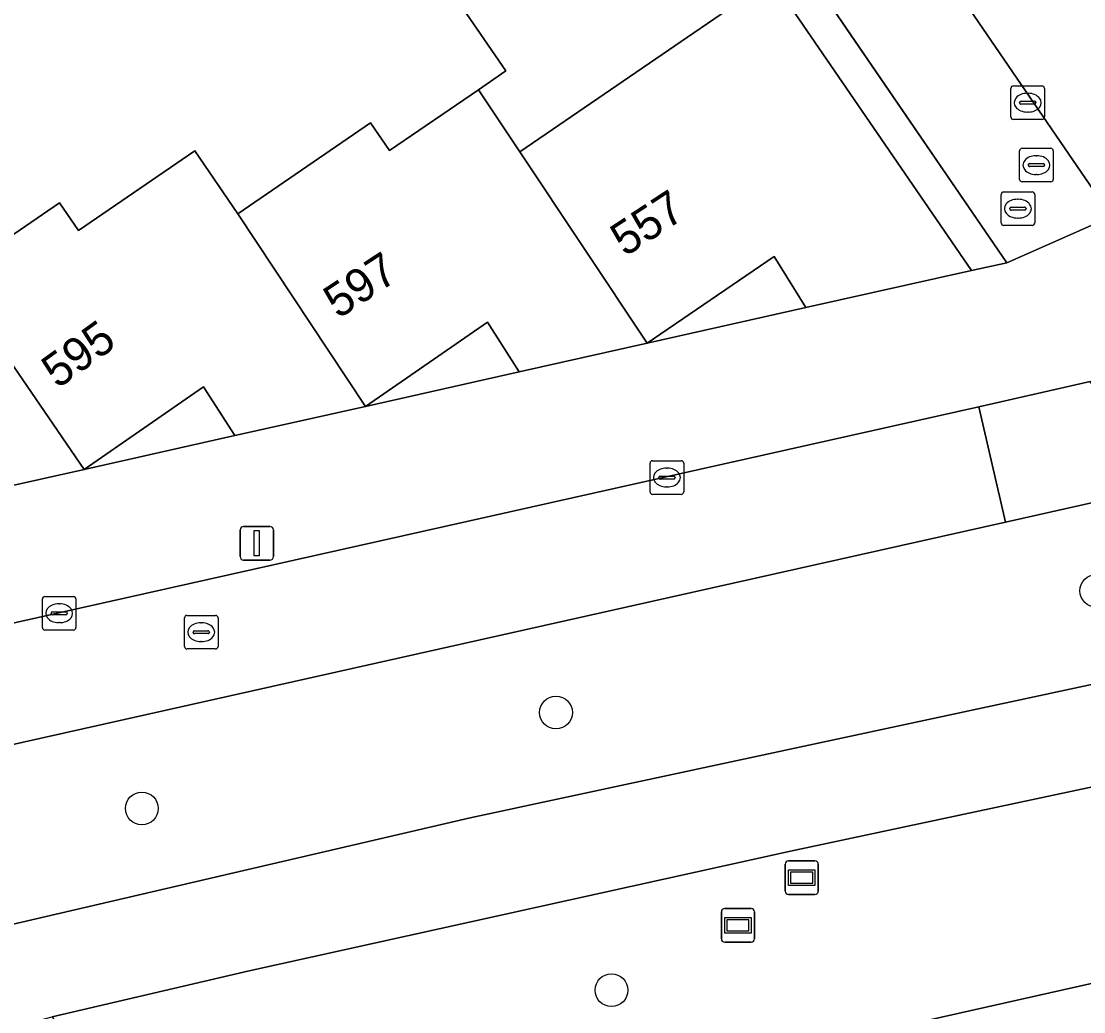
# Model space of a CAD drawing. Extents: x 155275 to 156265, y 382654 to 383635.
# Drawn here: x 155810.99 to 155842.67, y 383184.9 to 383214.43 of the extents above; entities that cross this region are included whole.
import ezdxf

# ---------------------------------------------------------------- set-up
doc = ezdxf.new("R2010")
doc.units = 0
for name, color, linetype in [('IMGEO_Berm_groen', 7, 'Continuous'), ('IMGEO_Boom', 7, 'Continuous'), ('IMGEO_Erf', 7, 'Continuous'), ('IMGEO_Fietspad_gesloten', 7, 'Continuous'), ('IMGEO_Kolk', 7, 'Continuous'), ('IMGEO_Lichtmast', 7, 'Continuous'), ('IMGEO_Pand', 7, 'Continuous'), ('IMGEO_Pand_nummerreeks', 7, 'Continuous'), ('IMGEO_Pand_overbouw', 7, 'Continuous'), ('IMGEO_Rijbaan_lokaal_gesloten', 7, 'Continuous'), ('IMGEO_Rijbaan_lokaal_open', 7, 'Continuous'), ('IMGEO_Rioolput', 7, 'Continuous'), ('IMGEO_Verklikker', 7, 'Continuous'), ('IMGEO_Voetpad_open', 7, 'Continuous')]:
    doc.layers.add(name, color=color, linetype=linetype)

msp = doc.modelspace()

# ---------------------------------------------------------------- linework, layer by layer
at = {"layer": 'IMGEO_Berm_groen'}
for points in [[(155848.276, 383195.813), (155845.025, 383200.548), (155840.331, 383199.496), (155810.33, 383192.781), (155806.938, 383192.022), (155810.141, 383187.373), (155824.371, 383190.683)], [(155849.792, 383187.297), (155853.53, 383188.156), (155850.109, 383193.138), (155833.92, 383189.687), (155817.791, 383186.119), (155811.916, 383184.748), (155815.412, 383179.591), (155819.804, 383180.555)]]:
    msp.add_lwpolyline(points, close=True, dxfattribs=at)
at = {"layer": 'IMGEO_Boom'}
for centre in [(155843.039, 383197.451), (155826.932, 383193.822), (155814.588, 383190.961), (155828.586, 383185.543)]:
    msp.add_circle(centre, 0.489, dxfattribs=at)
at = {"layer": 'IMGEO_Erf'}
for points in [[(155839.315, 383206.997), (155840.374, 383207.229), (155806.889, 383256.17), (155806.057, 383255.604), (155809.653, 383250.348), (155812.618, 383246.016), (155815.583, 383241.682), (155818.547, 383237.35), (155821.512, 383233.017), (155824.477, 383228.684), (155827.441, 383224.351), (155830.406, 383220.018), (155833.37, 383215.686)], [(155829.654, 383204.83), (155834.384, 383205.895), (155833.434, 383207.413)], [(155821.253, 383202.95), (155825.834, 383203.977), (155824.896, 383205.462)], [(155812.872, 383201.064), (155817.361, 383202.086), (155816.423, 383203.531)]]:
    msp.add_lwpolyline(points, close=True, dxfattribs=at)
msp.add_lwpolyline([(155800.38, 383217.68), (155803.347, 383213.349), (155807.304, 383207.574), (155808.057, 383208.09), (155808.925, 383206.823), (155812.132, 383209.02), (155812.697, 383208.195), (155816.162, 383210.569), (155817.448, 383208.691), (155821.408, 383211.404), (155821.973, 383210.579), (155824.618, 383212.391), (155825.438, 383212.953), (155823.731, 383215.445)], dxfattribs=at)
at = {"layer": 'IMGEO_Fietspad_gesloten'}
for points in [[(155890.991, 383205.663), (155886.832, 383204.488), (155883.25, 383203.59), (155879.663, 383202.712), (155851.768, 383196.574), (155848.276, 383195.813), (155824.371, 383190.683), (155810.141, 383187.373), (155807.023, 383186.593), (155784.144, 383180.465), (155758.942, 383174.226)], [(155803.789, 383182.688), (155808.796, 383183.946), (155811.916, 383184.748), (155817.791, 383186.119), (155833.92, 383189.687), (155850.109, 383193.138), (155853.636, 383193.872), (155881.496, 383200.022), (155885.113, 383200.876)]]:
    msp.add_lwpolyline(points, dxfattribs=at)
at = {"layer": 'IMGEO_Kolk'}
for p, q in [((155840.493, 383211.578), (155840.493, 383212.43)), ((155840.568, 383212.504), (155841.42, 383212.504)), ((155841.494, 383212.43), (155841.494, 383211.578)), ((155840.981, 383212.284), (155841.006, 383212.284)), ((155840.752, 383211.998), (155840.752, 383212.01)), ((155841.19, 383211.961), (155840.792, 383211.961)), ((155840.795, 383212.047), (155841.193, 383212.047)), ((155841.236, 383212.01), (155841.236, 383211.998)), ((155841.42, 383211.504), (155840.568, 383211.504)), ((155841.004, 383211.724), (155840.979, 383211.724)), ((155829.813, 383201.327), (155830.665, 383201.327)), ((155829.738, 383200.401), (155829.738, 383201.253)), ((155830.226, 383201.107), (155830.251, 383201.107)), ((155830.739, 383201.253), (155830.739, 383200.401)), ((155829.997, 383200.821), (155829.997, 383200.833)), ((155830.435, 383200.784), (155830.037, 383200.784)), ((155830.04, 383200.87), (155830.438, 383200.87)), ((155830.481, 383200.833), (155830.481, 383200.821)), ((155830.249, 383200.547), (155830.224, 383200.547)), ((155830.665, 383200.327), (155829.813, 383200.327)), ((155811.622, 383196.355), (155811.622, 383197.207)), ((155811.697, 383197.281), (155812.549, 383197.281)), ((155812.623, 383197.207), (155812.623, 383196.355)), ((155812.11, 383197.061), (155812.135, 383197.061)), ((155811.881, 383196.775), (155811.881, 383196.787)), ((155812.319, 383196.738), (155811.921, 383196.738)), ((155811.924, 383196.824), (155812.322, 383196.824)), ((155812.365, 383196.787), (155812.365, 383196.775)), ((155812.549, 383196.281), (155811.697, 383196.281)), ((155812.133, 383196.501), (155812.108, 383196.501))]:
    msp.add_line(p, q, dxfattribs=at)
for points in [[(155840.493, 383211.578), (155840.493, 383212.43)], [(155840.568, 383212.504), (155841.42, 383212.504)], [(155841.494, 383212.43), (155841.494, 383211.578)], [(155841.42, 383211.504), (155840.568, 383211.504)], [(155829.813, 383201.327), (155830.665, 383201.327)], [(155829.738, 383200.401), (155829.738, 383201.253)], [(155830.739, 383201.253), (155830.739, 383200.401)], [(155830.665, 383200.327), (155829.813, 383200.327)], [(155811.622, 383196.355), (155811.622, 383197.207)], [(155811.697, 383197.281), (155812.549, 383197.281)], [(155812.623, 383197.207), (155812.623, 383196.355)], [(155812.549, 383196.281), (155811.697, 383196.281)]]:
    msp.add_lwpolyline(points, dxfattribs=at)
for centre, radius, start, end in [((155840.57, 383212.428), 0.0765, 91.552, 178.448), ((155840.57, 383212.428), 0.0765, 91.552, 178.448), ((155841.418, 383212.428), 0.0765, 1.552, 88.448), ((155841.418, 383212.428), 0.0765, 1.552, 88.448), ((155840.792, 383212.007), 0.0403, 85.8775, 175.7526), ((155840.789, 383211.997), 0.0366, 178.938, 274.7102), ((155841.193, 383212.004), 0.043, 264.8664, 352.4533), ((155841.197, 383212.009), 0.0386, 1.7309, 96.639), ((155840.57, 383211.58), 0.0765, 181.552, 268.448), ((155840.57, 383211.58), 0.0765, 181.552, 268.448), ((155841.418, 383211.58), 0.0765, 271.552, 358.448), ((155841.418, 383211.58), 0.0765, 271.552, 358.448), ((155829.815, 383201.251), 0.0765, 91.552, 178.448), ((155829.815, 383201.251), 0.0765, 91.552, 178.448), ((155830.663, 383201.251), 0.0765, 1.552, 88.448), ((155830.663, 383201.251), 0.0765, 1.552, 88.448), ((155830.037, 383200.83), 0.0403, 85.8775, 175.7526), ((155830.034, 383200.82), 0.0366, 178.938, 274.7102), ((155830.438, 383200.827), 0.043, 264.8664, 352.4533), ((155830.442, 383200.832), 0.0386, 1.7309, 96.639), ((155829.815, 383200.403), 0.0765, 181.552, 268.448), ((155829.815, 383200.403), 0.0765, 181.552, 268.448), ((155830.663, 383200.403), 0.0765, 271.552, 358.448), ((155830.663, 383200.403), 0.0765, 271.552, 358.448), ((155811.699, 383197.205), 0.0765, 91.552, 178.448), ((155811.699, 383197.205), 0.0765, 91.552, 178.448), ((155812.547, 383197.205), 0.0765, 1.552, 88.448), ((155812.547, 383197.205), 0.0765, 1.552, 88.448), ((155811.921, 383196.784), 0.0403, 85.8775, 175.7526), ((155811.918, 383196.774), 0.0366, 178.938, 274.7102), ((155812.322, 383196.781), 0.043, 264.8664, 352.4533), ((155812.326, 383196.786), 0.0386, 1.7309, 96.639), ((155811.699, 383196.357), 0.0765, 181.552, 268.448), ((155811.699, 383196.357), 0.0765, 181.552, 268.448), ((155812.547, 383196.357), 0.0765, 271.552, 358.448), ((155812.547, 383196.357), 0.0765, 271.552, 358.448)]:
    msp.add_arc(centre, radius, start, end, dxfattribs=at)
for centre, major_axis, ratio, start_param, end_param in [((155840.98, 383212.004), (-0.387, 0.002), 0.722429, 4.712389, 7.853982), ((155841.005, 383212.004), (-0.39, 0.002), 0.717154, 1.570796, 4.712389), ((155830.225, 383200.827), (-0.387, 0.002), 0.722429, 4.712389, 7.853982), ((155830.25, 383200.827), (-0.39, 0.002), 0.717154, 1.570796, 4.712389), ((155812.109, 383196.781), (-0.387, 0.002), 0.722429, 4.712389, 7.853982), ((155812.134, 383196.781), (-0.39, 0.002), 0.717154, 1.570796, 4.712389)]:
    msp.add_ellipse(centre, major_axis=major_axis, ratio=ratio, start_param=start_param, end_param=end_param, dxfattribs=at)
at = {"layer": 'IMGEO_Lichtmast'}
for p, q in [((155817.517, 383198.469), (155817.517, 383199.269)), ((155817.517, 383199.269), (155817.517, 383198.469)), ((155817.617, 383199.369), (155818.407, 383199.369)), ((155818.407, 383199.369), (155817.617, 383199.369)), ((155818.507, 383199.269), (155818.507, 383198.469)), ((155818.507, 383198.469), (155818.507, 383199.269)), ((155818.407, 383198.369), (155817.617, 383198.369)), ((155817.617, 383198.369), (155818.407, 383198.369))]:
    msp.add_line(p, q, dxfattribs=at)
msp.add_lwpolyline([(155817.937, 383199.244), (155818.087, 383199.244), (155818.087, 383198.494), (155817.937, 383198.494), (155817.937, 383199.244)], dxfattribs=at)
for centre, start, end in [((155817.617, 383199.269), 90, 180), ((155817.617, 383199.269), 90, 180), ((155818.407, 383199.269), 0, 90), ((155818.407, 383199.269), 360, 90), ((155817.617, 383198.469), 180, 270), ((155817.617, 383198.469), 180, 270), ((155818.407, 383198.469), 270, 0), ((155818.407, 383198.469), 270, 0)]:
    msp.add_arc(centre, 0.1, start, end, dxfattribs=at)
at = {"layer": 'IMGEO_Pand'}
for points in [[(155833.37, 383215.686), (155830.406, 383220.018), (155823.731, 383215.445), (155825.438, 383212.953), (155824.618, 383212.391), (155825.854, 383210.535)], [(155833.37, 383215.686), (155825.854, 383210.535), (155829.654, 383204.83), (155833.434, 383207.413), (155834.384, 383205.895), (155839.315, 383206.997)], [(155817.448, 383208.691), (155821.253, 383202.95), (155824.896, 383205.462), (155825.834, 383203.977), (155829.654, 383204.83), (155825.854, 383210.535), (155824.618, 383212.391), (155821.973, 383210.579), (155821.408, 383211.404)], [(155817.448, 383208.691), (155816.162, 383210.569), (155812.697, 383208.195), (155812.132, 383209.02), (155808.925, 383206.823), (155812.872, 383201.064), (155816.423, 383203.531), (155817.361, 383202.086), (155821.253, 383202.95)], [(155808.925, 383206.823), (155808.057, 383208.09), (155807.304, 383207.574), (155800.774, 383203.1), (155803.59, 383198.984), (155806.855, 383201.265), (155807.785, 383199.931), (155812.872, 383201.064)]]:
    msp.add_lwpolyline(points, close=True, dxfattribs=at)
at = {"layer": 'IMGEO_Pand_overbouw'}
for points in [[(155839.315, 383206.997), (155840.374, 383207.229), (155834.199, 383216.254), (155833.37, 383215.686)], [(155821.253, 383202.95), (155825.834, 383203.977), (155824.896, 383205.462)], [(155812.872, 383201.064), (155817.361, 383202.086), (155816.423, 383203.531)]]:
    msp.add_lwpolyline(points, close=True, dxfattribs=at)
at = {"layer": 'IMGEO_Rijbaan_lokaal_gesloten'}
for points in [[(155840.331, 383199.496), (155839.534, 383202.939), (155809.577, 383196.225), (155810.33, 383192.781)], [(155819.804, 383180.555), (155820.572, 383177.109), (155850.604, 383183.856), (155849.792, 383187.297)]]:
    msp.add_lwpolyline(points, close=True, dxfattribs=at)
at = {"layer": 'IMGEO_Rijbaan_lokaal_open'}
msp.add_lwpolyline([(155789.533, 383282.828), (155777.762, 383266.885), (155770.477, 383257.018), (155750.942, 383230.559), (155753.136, 383227.355), (155767.095, 383206.967), (155771.224, 383200.936), (155773.915, 383197.049), (155790.895, 383199.943), (155792.328, 383200.159), (155792.43, 383196.787), (155793.032, 383196.885), (155797.086, 383197.846), (155798.734, 383198.236), (155786.907, 383215.526), (155772.43, 383236.689), (155783.237, 383244.091), (155793.514, 383251.129), (155807.738, 383260.872), (155811.353, 383255.588), (155821.26, 383241.107), (155827.482, 383232.012), (155843.488, 383208.615)], dxfattribs=at)
msp.add_lwpolyline([(155840.331, 383199.496), (155845.025, 383200.548), (155842.86, 383203.687), (155839.534, 383202.939)], close=True, dxfattribs=at)
at = {"layer": 'IMGEO_Rioolput'}
for p, q in [((155840.754, 383209.717), (155840.754, 383210.569)), ((155840.829, 383210.643), (155841.681, 383210.643)), ((155841.755, 383210.569), (155841.755, 383209.717)), ((155841.056, 383210.186), (155841.454, 383210.186)), ((155841.242, 383210.423), (155841.267, 383210.423)), ((155841.013, 383210.137), (155841.013, 383210.149)), ((155841.451, 383210.1), (155841.053, 383210.1)), ((155841.265, 383209.863), (155841.24, 383209.863)), ((155841.497, 383210.149), (155841.497, 383210.137)), ((155841.681, 383209.643), (155840.829, 383209.643)), ((155840.202, 383208.418), (155840.202, 383209.27)), ((155840.277, 383209.344), (155841.129, 383209.344)), ((155841.203, 383209.27), (155841.203, 383208.418)), ((155840.69, 383209.124), (155840.715, 383209.124)), ((155840.461, 383208.838), (155840.461, 383208.85)), ((155840.899, 383208.801), (155840.501, 383208.801)), ((155840.504, 383208.887), (155840.902, 383208.887)), ((155840.945, 383208.85), (155840.945, 383208.838)), ((155841.129, 383208.344), (155840.277, 383208.344)), ((155840.713, 383208.564), (155840.688, 383208.564)), ((155815.857, 383195.79), (155815.857, 383196.642)), ((155815.932, 383196.716), (155816.784, 383196.716)), ((155816.858, 383196.642), (155816.858, 383195.79)), ((155816.159, 383196.259), (155816.557, 383196.259)), ((155816.345, 383196.496), (155816.37, 383196.496)), ((155816.116, 383196.21), (155816.116, 383196.222)), ((155816.554, 383196.173), (155816.156, 383196.173)), ((155816.368, 383195.936), (155816.343, 383195.936)), ((155816.6, 383196.222), (155816.6, 383196.21)), ((155816.784, 383195.716), (155815.932, 383195.716))]:
    msp.add_line(p, q, dxfattribs=at)
for points in [[(155840.754, 383209.717), (155840.754, 383210.569)], [(155840.829, 383210.643), (155841.681, 383210.643)], [(155841.755, 383210.569), (155841.755, 383209.717)], [(155841.681, 383209.643), (155840.829, 383209.643)], [(155840.202, 383208.418), (155840.202, 383209.27)], [(155840.277, 383209.344), (155841.129, 383209.344)], [(155841.203, 383209.27), (155841.203, 383208.418)], [(155841.129, 383208.344), (155840.277, 383208.344)], [(155815.857, 383195.79), (155815.857, 383196.642)], [(155815.932, 383196.716), (155816.784, 383196.716)], [(155816.858, 383196.642), (155816.858, 383195.79)], [(155816.784, 383195.716), (155815.932, 383195.716)]]:
    msp.add_lwpolyline(points, dxfattribs=at)
for centre, radius, start, end in [((155840.831, 383210.567), 0.0765, 91.552, 178.448), ((155840.831, 383210.567), 0.0765, 91.552, 178.448), ((155841.679, 383210.567), 0.0765, 1.552, 88.448), ((155841.679, 383210.567), 0.0765, 1.552, 88.448), ((155841.053, 383210.146), 0.0403, 85.8775, 175.7526), ((155841.458, 383210.148), 0.0386, 1.7309, 96.639), ((155841.05, 383210.136), 0.0366, 178.938, 274.7102), ((155841.454, 383210.143), 0.043, 264.8664, 352.4533), ((155840.831, 383209.719), 0.0765, 181.552, 268.448), ((155840.831, 383209.719), 0.0765, 181.552, 268.448), ((155841.679, 383209.719), 0.0765, 271.552, 358.448), ((155841.679, 383209.719), 0.0765, 271.552, 358.448), ((155840.279, 383209.268), 0.0765, 91.552, 178.448), ((155840.279, 383209.268), 0.0765, 91.552, 178.448), ((155841.127, 383209.268), 0.0765, 1.552, 88.448), ((155841.127, 383209.268), 0.0765, 1.552, 88.448), ((155840.501, 383208.847), 0.0403, 85.8775, 175.7526), ((155840.498, 383208.837), 0.0366, 178.938, 274.7102), ((155840.902, 383208.844), 0.043, 264.8664, 352.4533), ((155840.906, 383208.849), 0.0386, 1.7309, 96.639), ((155840.279, 383208.42), 0.0765, 181.552, 268.448), ((155840.279, 383208.42), 0.0765, 181.552, 268.448), ((155841.127, 383208.42), 0.0765, 271.552, 358.448), ((155841.127, 383208.42), 0.0765, 271.552, 358.448), ((155815.934, 383196.64), 0.0765, 91.552, 178.448), ((155815.934, 383196.64), 0.0765, 91.552, 178.448), ((155816.782, 383196.64), 0.0765, 1.552, 88.448), ((155816.782, 383196.64), 0.0765, 1.552, 88.448), ((155816.156, 383196.219), 0.0403, 85.8775, 175.7526), ((155816.561, 383196.221), 0.0386, 1.7309, 96.639), ((155816.153, 383196.209), 0.0366, 178.938, 274.7102), ((155816.557, 383196.216), 0.043, 264.8664, 352.4533), ((155815.934, 383195.792), 0.0765, 181.552, 268.448), ((155815.934, 383195.792), 0.0765, 181.552, 268.448), ((155816.782, 383195.792), 0.0765, 271.552, 358.448), ((155816.782, 383195.792), 0.0765, 271.552, 358.448)]:
    msp.add_arc(centre, radius, start, end, dxfattribs=at)
for centre, major_axis, ratio, start_param, end_param in [((155841.241, 383210.143), (-0.387, 0.002), 0.722429, 4.712389, 7.853982), ((155841.266, 383210.143), (-0.39, 0.002), 0.717154, 1.570796, 4.712389), ((155840.689, 383208.844), (-0.387, 0.002), 0.722429, 4.712389, 7.853982), ((155840.714, 383208.844), (-0.39, 0.002), 0.717154, 1.570796, 4.712389), ((155816.344, 383196.216), (-0.387, 0.002), 0.722429, 4.712389, 7.853982), ((155816.369, 383196.216), (-0.39, 0.002), 0.717154, 1.570796, 4.712389)]:
    msp.add_ellipse(centre, major_axis=major_axis, ratio=ratio, start_param=start_param, end_param=end_param, dxfattribs=at)
at = {"layer": 'IMGEO_Verklikker'}
for p, q in [((155833.762, 383188.5), (155833.762, 383189.3)), ((155833.762, 383189.3), (155833.762, 383188.5)), ((155833.862, 383189.4), (155834.652, 383189.4)), ((155834.652, 383189.4), (155833.862, 383189.4)), ((155834.752, 383189.3), (155834.752, 383188.5)), ((155834.752, 383188.5), (155834.752, 383189.3)), ((155834.652, 383188.4), (155833.862, 383188.4)), ((155833.862, 383188.4), (155834.652, 383188.4)), ((155831.862, 383187.076), (155831.862, 383187.876)), ((155831.862, 383187.876), (155831.862, 383187.076)), ((155831.962, 383187.976), (155832.752, 383187.976)), ((155832.752, 383187.976), (155831.962, 383187.976)), ((155832.852, 383187.876), (155832.852, 383187.076)), ((155832.852, 383187.076), (155832.852, 383187.876)), ((155832.752, 383186.976), (155831.962, 383186.976)), ((155831.962, 383186.976), (155832.752, 383186.976))]:
    msp.add_line(p, q, dxfattribs=at)
for points in [[(155833.863, 383189.132), (155834.651, 383189.132), (155834.651, 383188.668), (155833.863, 383188.668), (155833.863, 383189.132)], [(155833.928, 383189.067), (155833.928, 383188.733), (155834.586, 383188.733), (155834.586, 383189.067), (155833.928, 383189.067)], [(155831.963, 383187.708), (155832.751, 383187.708), (155832.751, 383187.244), (155831.963, 383187.244), (155831.963, 383187.708)], [(155832.028, 383187.643), (155832.028, 383187.309), (155832.686, 383187.309), (155832.686, 383187.643), (155832.028, 383187.643)]]:
    msp.add_lwpolyline(points, dxfattribs=at)
for centre, start, end in [((155833.862, 383189.3), 90, 180), ((155833.862, 383189.3), 90, 180), ((155834.652, 383189.3), 0, 90), ((155834.652, 383189.3), 360, 90), ((155833.862, 383188.5), 180, 270), ((155833.862, 383188.5), 180, 270), ((155834.652, 383188.5), 270, 0), ((155834.652, 383188.5), 270, 0), ((155831.962, 383187.876), 90, 180), ((155831.962, 383187.876), 90, 180), ((155832.752, 383187.876), 0, 90), ((155832.752, 383187.876), 360, 90), ((155831.962, 383187.076), 180, 270), ((155831.962, 383187.076), 180, 270), ((155832.752, 383187.076), 270, 0), ((155832.752, 383187.076), 270, 0)]:
    msp.add_arc(centre, 0.1, start, end, dxfattribs=at)
at = {"layer": 'IMGEO_Voetpad_open'}
for points in [[(155777.993, 383236.404), (155785.416, 383241.471), (155786.19, 383240.364), (155788.309, 383241.815), (155790.427, 383243.266), (155789.665, 383244.381), (155795.193, 383248.159), (155795.954, 383247.044), (155797.672, 383248.223), (155799.39, 383249.402), (155798.628, 383250.516), (155806.057, 383255.604), (155806.889, 383256.17), (155840.374, 383207.229), (155843.488, 383208.615), (155827.482, 383232.012), (155821.26, 383241.107), (155811.353, 383255.588), (155807.738, 383260.872), (155793.514, 383251.129), (155783.237, 383244.091)], [(155849.412, 383209.926), (155843.488, 383208.615), (155840.374, 383207.229), (155839.315, 383206.997), (155834.384, 383205.895), (155829.654, 383204.83), (155825.834, 383203.977), (155821.253, 383202.95), (155817.361, 383202.086), (155812.872, 383201.064), (155807.785, 383199.931), (155803.59, 383198.984), (155802.561, 383198.744), (155798.734, 383198.236), (155797.086, 383197.846)], [(155839.534, 383202.939), (155842.86, 383203.687), (155846.351, 383204.438), (155846.877, 383204.556)], [(155801.654, 383194.468), (155804.8, 383195.157), (155809.577, 383196.225), (155839.534, 383202.939)]]:
    msp.add_lwpolyline(points, dxfattribs=at)

# ---------------------------------------------------------------- texts
at = {"layer": 'IMGEO_Pand_nummerreeks'}
for s, rotation, p in [('557', 33.2317, (155828.992, 383207.393)), ('597', 33.4166, (155820.442, 383205.54)), ('595', 36.0274, (155812.077, 383203.457))]:
    msp.add_text(s, height=1, rotation=rotation, dxfattribs=at).set_placement(p)

doc.saveas('drawing.dxf')
